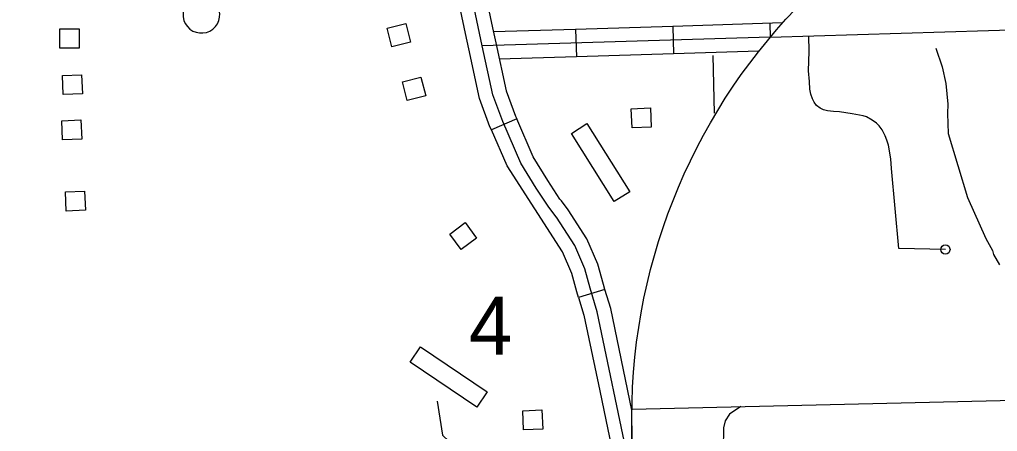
# Model space of a CAD drawing. Extents: x 1671357 to 13005564, y 567358 to 14261451.
# Drawn here: x 12758300.93 to 12758311, y 14259888.15 to 14259892.4 of the extents above; entities that cross this region are included whole.
import ezdxf

# ---------------------------------------------------------------- set-up
doc = ezdxf.new("R2010")
doc.units = 0
for name, color, linetype in [('31', 7, 'Continuous'), ('32', 7, 'Continuous'), ('35', 7, 'Continuous'), ('5', 7, 'Continuous'), ('56', 7, 'Continuous'), ('63', 7, 'Continuous')]:
    doc.layers.add(name, color=color, linetype=linetype)

msp = doc.modelspace()

# ---------------------------------------------------------------- linework, layer by layer
at = {"layer": '31'}
msp.add_line((12758306.045, 14259891.375), (12758305.784, 14259891.262), dxfattribs=at)
for points in [[(12758306.462, 14259890.351), (12758306.375, 14259890.465), (12758306.245, 14259890.662), (12758306.088, 14259890.919), (12758305.902, 14259891.348), (12758305.799, 14259891.623), (12758305.69, 14259892.127), (12758305.407, 14259893.468), (12758304.951, 14259895.115), (12758304.842, 14259895.392), (12758304.709, 14259895.597), (12758304.586, 14259895.721), (12758304.402, 14259895.83), (12758304.012, 14259895.943), (12758302.995, 14259896.159), (12758301.991, 14259896.352), (12758301.523, 14259896.462), (12758301.349, 14259896.557), (12758301.191, 14259896.664), (12758301.039, 14259896.729), (12758300.936, 14259896.756), (12758300.742, 14259896.754), (12758295.585, 14259896.593)], [(12758305.518, 14259892.253), (12758305.311, 14259893.232)], [(12758305.589, 14259893.29), (12758305.796, 14259892.312)], [(12758305.796, 14259892.312), (12758305.829, 14259892.157), (12758305.936, 14259891.663), (12758306.034, 14259891.401), (12758306.045, 14259891.375)], [(12758305.784, 14259891.262), (12758305.77, 14259891.294), (12758305.662, 14259891.583), (12758305.551, 14259892.097), (12758305.518, 14259892.253)], [(12758306.505, 14259890.53), (12758306.491, 14259890.548), (12758306.365, 14259890.738), (12758306.215, 14259890.985), (12758306.045, 14259891.375)], [(12758305.946, 14259890.889), (12758305.784, 14259891.262)], [(12758306.682, 14259889.533), (12758306.665, 14259889.591), (12758306.613, 14259889.782), (12758306.517, 14259890.003), (12758305.946, 14259890.889)], [(12758306.954, 14259889.615), (12758306.938, 14259889.669), (12758306.882, 14259889.876), (12758306.769, 14259890.137), (12758306.575, 14259890.437), (12758306.505, 14259890.53)], [(12758307.266, 14259887.627), (12758307.249, 14259887.664), (12758307.2, 14259887.826), (12758306.875, 14259889.385), (12758306.801, 14259889.63), (12758306.747, 14259889.829), (12758306.643, 14259890.07), (12758306.456, 14259890.36)]]:
    msp.add_lwpolyline(points, dxfattribs=at)
msp.add_lwpolyline([(12758306.682, 14259889.533), (12758306.737, 14259889.35), (12758306.9, 14259888.57), (12758307.063, 14259887.791), (12758307.116, 14259887.614), (12758307.321, 14259887.245), (12758307.25, 14259887.832), (12758307.232, 14259888.097), (12758307.232, 14259888.372), (12758307.013, 14259889.42), (12758306.954, 14259889.615)], close=True, dxfattribs=at)
at = {"layer": '32'}
for p, q in [((12758307.652, 14259892.328), (12758307.661, 14259892.044)), ((12758308.652, 14259892.359), (12758308.656, 14259892.217)), ((12758306.652, 14259892.297), (12758306.661, 14259892.013))]:
    msp.add_line(p, q, dxfattribs=at)
for points in [[(12758308.656, 14259892.217), (12758313.153, 14259892.354), (12758317.747, 14259892.528)], [(12758307.652, 14259892.328), (12758306.652, 14259892.297)], [(12758308.782, 14259892.363), (12758307.652, 14259892.328)], [(12758308.656, 14259892.217), (12758305.691, 14259892.126)], [(12758306.652, 14259892.297), (12758305.805, 14259892.271)], [(12758310.46, 14259890.028), (12758309.979, 14259890.037), (12758309.906, 14259890.862), (12758309.898, 14259890.962), (12758309.873, 14259891.102), (12758309.857, 14259891.154), (12758309.838, 14259891.201), (12758309.81, 14259891.26), (12758309.778, 14259891.303), (12758309.75, 14259891.33), (12758309.707, 14259891.362), (12758309.649, 14259891.394), (12758309.612, 14259891.407), (12758309.501, 14259891.427), (12758309.369, 14259891.448), (12758309.309, 14259891.451), (12758309.246, 14259891.457), (12758309.204, 14259891.467), (12758309.169, 14259891.484), (12758309.133, 14259891.511), (12758309.109, 14259891.548), (12758309.092, 14259891.58), (12758309.075, 14259891.628), (12758309.065, 14259891.681), (12758309.061, 14259891.761), (12758309.049, 14259891.868), (12758309.058, 14259892.07), (12758309.053, 14259892.229)], [(12758306.661, 14259892.013), (12758305.865, 14259891.989)], [(12758307.661, 14259892.044), (12758306.661, 14259892.013)], [(12758308.538, 14259892.071), (12758307.661, 14259892.044)], [(12758307.232, 14259888.384), (12758313.213, 14259888.524)], [(12758308.353, 14259888.41), (12758308.237, 14259888.331), (12758308.192, 14259888.263), (12758308.174, 14259888.192), (12758308.156, 14259887.09)]]:
    msp.add_lwpolyline(points, dxfattribs=at)
msp.add_circle((12758310.46, 14259890.028), 0.0474, dxfattribs=at)
msp.add_arc((12758302.798, 14259892.448), 0.189, 132.3672, 36.097, dxfattribs=at)
at = {"layer": '35'}
msp.add_lwpolyline([(12758310.361, 14259892.103), (12758310.426, 14259891.912), (12758310.465, 14259891.739), (12758310.486, 14259891.525), (12758310.48, 14259891.43), (12758310.489, 14259891.225), (12758310.689, 14259890.565), (12758310.876, 14259890.141), (12758310.945, 14259890.017), (12758310.956, 14259889.977), (12758311.018, 14259889.87)], dxfattribs=at)
at = {"layer": '5'}
msp.add_lwpolyline([(12758308.064, 14259892.029), (12758308.08, 14259891.434)], dxfattribs=at)
at = {"layer": '56'}
for points in [[(12758304.76, 14259892.117), (12758304.711, 14259892.308), (12758304.902, 14259892.357), (12758304.952, 14259892.166)], [(12758301.342, 14259892.105), (12758301.342, 14259892.302), (12758301.539, 14259892.302), (12758301.539, 14259892.105)], [(12758301.375, 14259891.625), (12758301.367, 14259891.822), (12758301.564, 14259891.83), (12758301.573, 14259891.633)], [(12758304.917, 14259891.564), (12758304.868, 14259891.755), (12758305.059, 14259891.804), (12758305.108, 14259891.613)], [(12758307.233, 14259891.282), (12758307.225, 14259891.479), (12758307.423, 14259891.487), (12758307.431, 14259891.29)], [(12758301.369, 14259891.157), (12758301.361, 14259891.354), (12758301.558, 14259891.363), (12758301.567, 14259891.166)], [(12758306.609, 14259891.225), (12758306.769, 14259891.326), (12758307.21, 14259890.624), (12758307.05, 14259890.523)], [(12758301.407, 14259890.425), (12758301.398, 14259890.622), (12758301.596, 14259890.63), (12758301.604, 14259890.433)], [(12758305.472, 14259890.029), (12758305.355, 14259890.187), (12758305.514, 14259890.305), (12758305.631, 14259890.146)], [(12758304.949, 14259888.867), (12758305.055, 14259889.024), (12758305.742, 14259888.56), (12758305.636, 14259888.403)], [(12758306.116, 14259888.17), (12758306.108, 14259888.367), (12758306.305, 14259888.375), (12758306.314, 14259888.178)]]:
    msp.add_lwpolyline(points, close=True, dxfattribs=at)
msp.add_lwpolyline([(12758305.226, 14259888.466), (12758305.28, 14259888.116), (12758306.184, 14259887.256)], dxfattribs=at)
at = {"layer": '63'}
msp.add_circle((12758313.341, 14259888.294), 6.11, dxfattribs=at)

# ---------------------------------------------------------------- texts
at = {"layer": '56'}
msp.add_text('4', height=0.6, dxfattribs=at).set_placement((12758305.554, 14259888.943))

doc.saveas('drawing.dxf')
